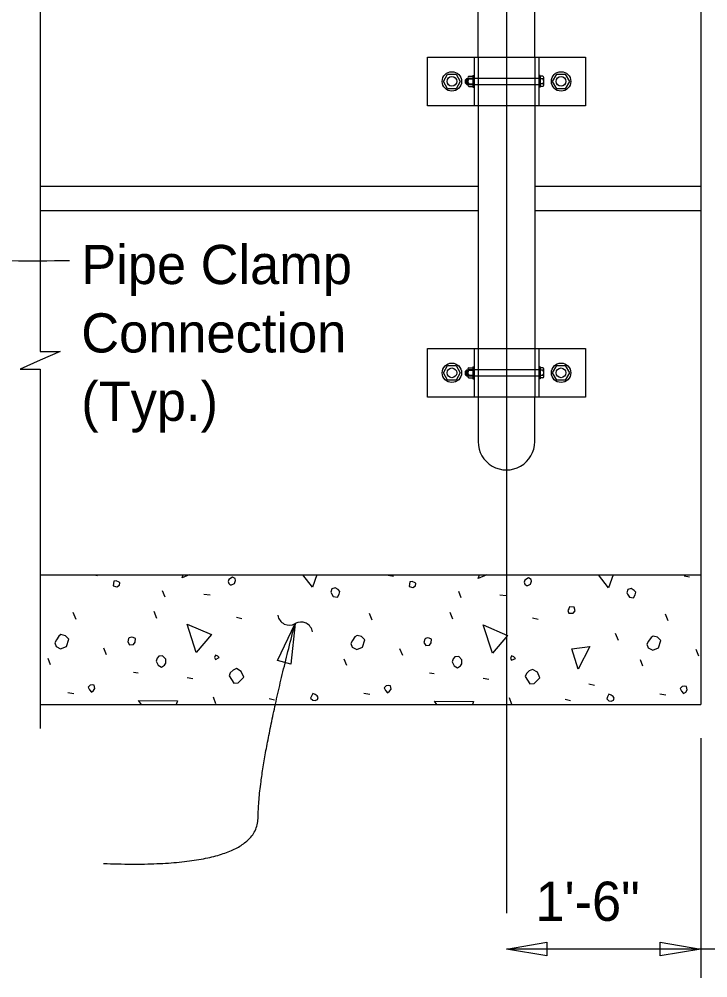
# Model space of a CAD drawing. Extents: x 0 to 72.1, y -7 to 30.
# Drawn here: x 23.751 to 27.295, y 14.116 to 19.05 of the extents above; entities that cross this region are included whole.
import ezdxf

# ---------------------------------------------------------------- set-up
doc = ezdxf.new("R2010")
doc.units = 0
for name, color, linetype in [('AdhocPoint_dp', 7, 'Continuous'), ('Border', 7, 'Continuous'), ('Patterning', 7, 'Continuous'), ('PlotBorder_dp', 7, 'Continuous'), ('SheetBorder_dp', 7, 'Continuous'), ('TextMisc', 7, 'Continuous'), ('TextStructures', 7, 'Continuous')]:
    doc.layers.add(name, color=color, linetype=linetype)

msp = doc.modelspace()

# ---------------------------------------------------------------- linework, layer by layer
at = {"layer": 'AdhocPoint_dp'}
for p, q in [((26.0514, 18.7229), (26.0514, 18.735)), ((26.0571, 18.7229), (26.0571, 18.735)), ((26.0514, 17.2229), (26.0514, 17.235)), ((26.0571, 17.2229), (26.0571, 17.235)), ((24.1346, 16.1899), (24.1533, 16.1862)), ((25.6506, 16.1879), (25.6772, 16.1826)), ((27.1745, 16.1844), (27.201, 16.1791)), ((24.5016, 16.0748), (24.4892, 16.1084)), ((24.7014, 16.0907), (24.7332, 16.0872)), ((26.0254, 16.0713), (26.013, 16.1049)), ((26.2252, 16.0872), (26.257, 16.0836)), ((24.0437, 15.9599), (24.0296, 15.9953)), ((24.4592, 15.9652), (24.445, 16.0006)), ((25.5676, 15.9564), (25.5534, 15.9917)), ((25.983, 15.9617), (25.9688, 15.997)), ((27.0914, 15.9528), (27.0772, 15.9882)), ((24.8693, 15.9723), (24.8976, 15.9652)), ((26.3931, 15.9687), (26.4214, 15.9617)), ((26.835, 15.8521), (26.8209, 15.8874)), ((24.2011, 15.7778), (24.1869, 15.8132)), ((25.7249, 15.7743), (25.7108, 15.8096)), ((27.2487, 15.7708), (27.2346, 15.8061)), ((23.9129, 15.7266), (23.9006, 15.7601)), ((25.4367, 15.723), (25.4244, 15.7566)), ((26.9606, 15.7195), (26.9482, 15.7531)), ((24.339, 15.6894), (24.3637, 15.6859)), ((24.6147, 15.6612), (24.6448, 15.6559)), ((25.8628, 15.6859), (25.8875, 15.6824)), ((26.1385, 15.6576), (26.1686, 15.6523)), ((26.683, 15.6293), (26.7113, 15.6223)), ((24.0013, 15.5851), (24.0314, 15.5798)), ((24.7632, 15.5268), (24.7509, 15.5604)), ((25.0372, 15.5533), (25.0655, 15.5462)), ((25.5251, 15.5816), (25.5552, 15.5763)), ((26.287, 15.5233), (26.2747, 15.5569)), ((26.561, 15.5498), (26.5893, 15.5427)), ((27.0489, 15.5781), (27.079, 15.5728))]:
    msp.add_line(p, q, dxfattribs=at)
for points in [[(24.59, 16.1738), (24.5949, 16.1899)], [(24.6259, 16.1899), (24.59, 16.1738)], [(25.26, 16.1261), (25.2114, 16.1899)], [(25.2838, 16.1899), (25.26, 16.1261)], [(26.1138, 16.1703), (26.1199, 16.1899)], [(26.1576, 16.1899), (26.1138, 16.1703)], [(26.7838, 16.1225), (26.7326, 16.1899)], [(26.809, 16.1899), (26.7838, 16.1225)], [(24.2347, 16.1331), (24.2541, 16.1278), (24.2665, 16.1367), (24.2683, 16.1491), (24.2647, 16.1526), (24.2506, 16.1597), (24.2382, 16.1579), (24.2364, 16.1455), (24.2347, 16.1331)], [(24.8375, 16.1385), (24.8445, 16.1385), (24.8587, 16.1455), (24.864, 16.1614), (24.8622, 16.1703), (24.8481, 16.1773), (24.8304, 16.1667), (24.8269, 16.1561), (24.8304, 16.1455), (24.8375, 16.1385)], [(25.7585, 16.1296), (25.7779, 16.1243), (25.7903, 16.1331), (25.7921, 16.1455), (25.7885, 16.1491), (25.7744, 16.1561), (25.762, 16.1544), (25.7602, 16.142), (25.7585, 16.1296)], [(26.3613, 16.1349), (26.3684, 16.1349), (26.3825, 16.142), (26.3878, 16.1579), (26.386, 16.1667), (26.3719, 16.1738), (26.3542, 16.1632), (26.3507, 16.1526), (26.3542, 16.142), (26.3613, 16.1349)], [(25.359, 16.0943), (25.3678, 16.0783), (25.389, 16.0748), (25.3979, 16.0907), (25.4014, 16.1049), (25.3926, 16.1137), (25.3766, 16.1225), (25.3607, 16.1172), (25.3554, 16.1013), (25.359, 16.0943)], [(26.8828, 16.0907), (26.8916, 16.0748), (26.9128, 16.0713), (26.9217, 16.0872), (26.9252, 16.1013), (26.9164, 16.1102), (26.9005, 16.119), (26.8845, 16.1137), (26.8792, 16.0978), (26.8828, 16.0907)], [(26.5805, 15.9935), (26.6017, 15.9935), (26.6123, 16.0041), (26.607, 16.0235), (26.584, 16.0253), (26.5805, 16.0147), (26.5752, 16.0059), (26.5805, 15.9935), (26.577, 15.997)], [(24.6625, 15.7902), (24.6147, 15.9369), (24.7402, 15.8821), (24.6625, 15.7902)], [(26.1863, 15.7867), (26.1385, 15.9334), (26.2641, 15.8786), (26.1863, 15.7867)], [(23.9412, 15.822), (23.9642, 15.8096), (23.9942, 15.822), (24.0066, 15.8591), (23.9889, 15.8768), (23.966, 15.8821), (23.9554, 15.8751), (23.943, 15.8556), (23.9341, 15.8397), (23.9412, 15.822)], [(24.3107, 15.845), (24.3195, 15.8291), (24.339, 15.8309), (24.3478, 15.8432), (24.3496, 15.8627), (24.3372, 15.868), (24.3284, 15.8698), (24.3177, 15.8662), (24.3142, 15.8627), (24.3107, 15.845)], [(25.465, 15.8185), (25.488, 15.8061), (25.5181, 15.8185), (25.5304, 15.8556), (25.5128, 15.8733), (25.4898, 15.8786), (25.4792, 15.8715), (25.4668, 15.8521), (25.458, 15.8362), (25.465, 15.8185)], [(25.8345, 15.8415), (25.8433, 15.8256), (25.8628, 15.8273), (25.8716, 15.8397), (25.8734, 15.8591), (25.861, 15.8644), (25.8522, 15.8662), (25.8416, 15.8627), (25.838, 15.8591), (25.8345, 15.8415)], [(26.9888, 15.8149), (27.0118, 15.8026), (27.0419, 15.8149), (27.0543, 15.8521), (27.0366, 15.8698), (27.0136, 15.8751), (27.003, 15.868), (26.9906, 15.8485), (26.9818, 15.8326), (26.9888, 15.8149)], [(26.6282, 15.7053), (26.5946, 15.8096), (26.6883, 15.822), (26.6282, 15.7053)], [(24.4556, 15.746), (24.4662, 15.7248), (24.4839, 15.7142), (24.4981, 15.7248), (24.5051, 15.7354), (24.5051, 15.7566), (24.4892, 15.7725), (24.4698, 15.7708), (24.4609, 15.7619), (24.4556, 15.746)], [(24.7615, 15.7548), (24.7809, 15.7637), (24.7738, 15.7708), (24.7615, 15.7761), (24.7562, 15.7637), (24.7615, 15.7548)], [(25.9795, 15.7425), (25.9901, 15.7213), (26.0077, 15.7107), (26.0219, 15.7213), (26.0289, 15.7319), (26.0289, 15.7531), (26.013, 15.769), (25.9936, 15.7672), (25.9848, 15.7584), (25.9795, 15.7425)], [(26.2853, 15.7513), (26.3047, 15.7601), (26.2976, 15.7672), (26.2853, 15.7725), (26.28, 15.7601), (26.2853, 15.7513)], [(24.8322, 15.67), (24.8552, 15.6329), (24.8781, 15.6346), (24.887, 15.6435), (24.9064, 15.6629), (24.894, 15.693), (24.8693, 15.7071), (24.8516, 15.7), (24.8375, 15.6859), (24.8322, 15.67)], [(26.356, 15.6665), (26.379, 15.6293), (26.4019, 15.6311), (26.4108, 15.6399), (26.4302, 15.6594), (26.4179, 15.6894), (26.3931, 15.7036), (26.3754, 15.6965), (26.3613, 15.6824), (26.356, 15.6665)], [(24.1127, 15.5975), (24.1233, 15.5869), (24.1339, 15.594), (24.141, 15.6046), (24.1374, 15.6223), (24.1286, 15.624), (24.1162, 15.6223), (24.1056, 15.6117), (24.1127, 15.5975)], [(25.6365, 15.594), (25.6471, 15.5834), (25.6577, 15.5904), (25.6648, 15.601), (25.6613, 15.6187), (25.6524, 15.6205), (25.64, 15.6187), (25.6294, 15.6081), (25.6365, 15.594)], [(27.1603, 15.5904), (27.1709, 15.5798), (27.1815, 15.5869), (27.1886, 15.5975), (27.1851, 15.6152), (27.1762, 15.617), (27.1639, 15.6152), (27.1532, 15.6046), (27.1603, 15.5904)], [(24.3803, 15.5233), (24.3655, 15.5427), (24.5652, 15.5409), (24.5586, 15.5233)], [(25.2617, 15.5445), (25.2741, 15.5427), (25.2865, 15.548), (25.29, 15.5586), (25.2847, 15.5675), (25.2741, 15.5745), (25.2617, 15.5798), (25.2547, 15.5657), (25.2511, 15.5551), (25.2617, 15.5445)], [(26.7856, 15.5409), (26.7979, 15.5392), (26.8103, 15.5445), (26.8138, 15.5551), (26.8085, 15.5639), (26.7979, 15.571), (26.7856, 15.5763), (26.7785, 15.5622), (26.7749, 15.5516), (26.7856, 15.5409)], [(25.9014, 15.5233), (25.8893, 15.5392), (26.0891, 15.5374), (26.0838, 15.5233)]]:
    msp.add_lwpolyline(points, dxfattribs=at)
at = {"layer": 'Border'}
for p, q in [((27.2589, 15.3499), (27.2589, 14.1158)), ((28.5923, 14.2638), (26.2589, 14.2638))]:
    msp.add_line(p, q, dxfattribs=at)
msp.add_lwpolyline([(23.8591, 19.1899), (23.8591, 17.3393), (23.9624, 17.3393), (23.8591, 17.2943), (23.7558, 17.2493), (23.8591, 17.2493), (23.8591, 15.3986)], dxfattribs=at)
for points in [[(25.1706, 15.9395), (25.1484, 15.7295), (25.0805, 15.7485)], [(26.2589, 14.2639), (26.4672, 14.2992), (26.4672, 14.2286)], [(27.2589, 14.2639), (27.0507, 14.2286), (27.0507, 14.2992)]]:
    msp.add_lwpolyline(points, close=True, dxfattribs=at)
for centre, start, end in [((25.1415, 15.9906), 188.4294, 300.1567), ((25.2014, 15.8876), 8.4294, 120.1567)]:
    msp.add_arc(centre, 0.0596, start, end, dxfattribs=at)
for points in [[(24.0093, 17.8067), (23.0559, 17.7774), (23.3778, 18.3094), (23.4593, 18.6436), (22.9495, 18.722), (22.6282, 18.7321)], [(24.1845, 14.704), (24.98, 14.6743), (24.9817, 15.2106), (25.1708, 15.9393)]]:
    msp.add_open_spline(points, degree=2, dxfattribs=at)
at = {"layer": 'Patterning'}
for p, q in [((26.1131, 18.8548), (26.1131, 18.6048)), ((26.4048, 18.8548), (26.4048, 18.6048)), ((26.4256, 18.7444), (26.0608, 18.7444)), ((26.0608, 18.7145), (26.4256, 18.7145)), ((26.1131, 17.3548), (26.1131, 17.1048)), ((26.4048, 17.3548), (26.4048, 17.1048)), ((26.4256, 17.2444), (26.0608, 17.2444)), ((26.0608, 17.2145), (26.4256, 17.2145))]:
    msp.add_line(p, q, dxfattribs=at)
at = {"layer": 'PlotBorder_dp'}
for p, q in [((26.1131, 18.8548), (26.1131, 19.3307)), ((26.4048, 18.8548), (26.4048, 19.3307)), ((25.853, 18.8548), (26.665, 18.8548)), ((25.853, 18.6048), (25.853, 18.8548)), ((26.0923, 18.8548), (26.0923, 18.6048)), ((26.4256, 18.8548), (26.4256, 18.6048)), ((26.665, 18.8548), (26.665, 18.6048)), ((26.0656, 18.7558), (26.0858, 18.7558)), ((26.0858, 18.7601), (26.0858, 18.6995)), ((26.0858, 18.7601), (26.0923, 18.7601)), ((26.0858, 18.7558), (26.0858, 18.7039)), ((26.4319, 18.7601), (26.4259, 18.7601)), ((26.4319, 18.7601), (26.4319, 18.6995)), ((26.4466, 18.7558), (26.4319, 18.7558)), ((26.0486, 18.7378), (26.0542, 18.7444)), ((26.0486, 18.7201), (26.0486, 18.7378)), ((26.0486, 18.7201), (26.0542, 18.7145)), ((26.0542, 18.7444), (26.0608, 18.7444)), ((26.0542, 18.7145), (26.0542, 18.7444)), ((26.0542, 18.7145), (26.0608, 18.7145)), ((26.0608, 18.7477), (26.0608, 18.712)), ((26.0654, 18.7428), (26.0858, 18.7428)), ((26.0654, 18.7169), (26.0858, 18.7169)), ((26.0658, 18.7039), (26.0858, 18.7039)), ((26.4468, 18.7428), (26.4319, 18.7428)), ((26.4468, 18.7168), (26.4319, 18.7168)), ((26.4466, 18.7038), (26.4319, 18.7038)), ((26.4517, 18.7104), (26.4517, 18.7493)), ((26.0858, 18.6995), (26.0923, 18.6995)), ((26.4319, 18.6995), (26.4259, 18.6995)), ((26.665, 18.6048), (25.853, 18.6048)), ((26.1131, 18.6048), (26.1131, 17.3548)), ((26.4048, 18.6048), (26.4048, 17.3548)), ((25.853, 17.3548), (26.665, 17.3548)), ((25.853, 17.1048), (25.853, 17.3548)), ((26.0923, 17.3548), (26.0923, 17.1048)), ((26.4256, 17.3548), (26.4256, 17.1048)), ((26.665, 17.3548), (26.665, 17.1048)), ((26.0486, 17.2378), (26.0542, 17.2444)), ((26.0486, 17.2201), (26.0486, 17.2378)), ((26.0542, 17.2444), (26.0608, 17.2444)), ((26.0542, 17.2145), (26.0542, 17.2444)), ((26.0608, 17.2477), (26.0608, 17.212)), ((26.0654, 17.2428), (26.0858, 17.2428)), ((26.0656, 17.2558), (26.0858, 17.2558)), ((26.0858, 17.2601), (26.0858, 17.1995)), ((26.0858, 17.2601), (26.0923, 17.2601)), ((26.0858, 17.2558), (26.0858, 17.2039)), ((26.4319, 17.2601), (26.4259, 17.2601)), ((26.4319, 17.2601), (26.4319, 17.1995)), ((26.4466, 17.2558), (26.4319, 17.2558)), ((26.4468, 17.2428), (26.4319, 17.2428)), ((26.4517, 17.2104), (26.4517, 17.2493)), ((26.0486, 17.2201), (26.0542, 17.2145)), ((26.0542, 17.2145), (26.0608, 17.2145)), ((26.0654, 17.2169), (26.0858, 17.2169)), ((26.0658, 17.2039), (26.0858, 17.2039)), ((26.0858, 17.1995), (26.0923, 17.1995)), ((26.4319, 17.1995), (26.4259, 17.1995)), ((26.4468, 17.2168), (26.4319, 17.2168)), ((26.4466, 17.2038), (26.4319, 17.2038)), ((26.665, 17.1048), (25.853, 17.1048)), ((26.113, 17.1048), (26.113, 16.8757)), ((26.4047, 16.8757), (26.4047, 17.1048))]:
    msp.add_line(p, q, dxfattribs=at)
for points in [[(25.9563, 18.7674), (25.9997, 18.7674), (26.0213, 18.7298), (25.9997, 18.6923), (25.9563, 18.6923), (25.9346, 18.7298)], [(26.5183, 18.7674), (26.5616, 18.7674), (26.5833, 18.7298), (26.5616, 18.6923), (26.5183, 18.6923), (26.4966, 18.7298)], [(25.9563, 17.2674), (25.9997, 17.2674), (26.0213, 17.2298), (25.9997, 17.1923), (25.9563, 17.1923), (25.9346, 17.2298)], [(26.5183, 17.2674), (26.5616, 17.2674), (26.5833, 17.2298), (26.5616, 17.1923), (26.5183, 17.1923), (26.4966, 17.2298)]]:
    msp.add_lwpolyline(points, close=True, dxfattribs=at)
for centre, radius in [((25.978, 18.7298), 0.05), ((25.978, 18.7298), 0.025), ((26.54, 18.7298), 0.05), ((26.54, 18.7298), 0.025), ((25.978, 17.2298), 0.05), ((26.54, 17.2298), 0.05), ((25.978, 17.2298), 0.025), ((26.54, 17.2298), 0.025)]:
    msp.add_circle(centre, radius, dxfattribs=at)
for centre, radius, start, end in [((26.0673, 18.7493), 0.00674, 104.4891, 254.1889), ((26.4449, 18.7493), 0.00673, 285.7823, 75.5404), ((26.0802, 18.7298), 0.0196, 138.628, 221.372), ((26.0673, 18.7104), 0.00673, 105.7823, 255.5404), ((26.4449, 18.7104), 0.00674, 284.4891, 74.1889), ((26.432, 18.7298), 0.0196, 318.628, 41.372), ((26.0673, 17.2493), 0.00674, 104.4891, 254.1889), ((26.0802, 17.2298), 0.0196, 138.628, 221.372), ((26.4449, 17.2493), 0.00673, 285.7823, 75.5404), ((26.432, 17.2298), 0.0196, 318.628, 41.372), ((26.0673, 17.2104), 0.00673, 105.7823, 255.5404), ((26.4449, 17.2104), 0.00674, 284.4891, 74.1889)]:
    msp.add_arc(centre, radius, start, end, dxfattribs=at)
msp.add_ellipse((26.2589, 16.8757), major_axis=(0, 0.1458), ratio=0.999499, start_param=1.570796, end_param=4.712389, dxfattribs=at)
at = {"layer": 'SheetBorder_dp'}
msp.add_line((26.2589, 27.5581), (26.2589, 14.4491), dxfattribs=at)
at = {"layer": 'TextMisc'}
for p, q in [((27.2589, 19.1899), (27.2589, 15.5233)), ((23.8591, 18.1899), (26.1131, 18.1899)), ((26.4048, 18.1899), (27.2588, 18.1899)), ((23.8591, 18.0649), (26.1131, 18.0649)), ((26.4048, 18.0649), (27.2588, 18.0649)), ((23.8591, 16.1899), (27.2589, 16.1899)), ((23.8591, 15.5233), (27.2589, 15.5233))]:
    msp.add_line(p, q, dxfattribs=at)

# ---------------------------------------------------------------- texts
at = {"layer": 'Border'}
for s, p in [('Pipe Clamp ', (24.0705, 17.6864)), ('Connection ', (24.0705, 17.3344)), ('(Typ.)', (24.0705, 16.9824))]:
    msp.add_text(s, height=0.2016, dxfattribs=at).set_placement(p)
at = {"layer": 'TextStructures'}
msp.add_text('1\'-6"', height=0.2016, dxfattribs=at).set_placement((26.4083, 14.4091))

doc.saveas('drawing.dxf')
